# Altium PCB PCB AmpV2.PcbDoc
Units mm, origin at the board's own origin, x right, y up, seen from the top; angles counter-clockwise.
Board outline 98.3 x 139.06 mm, 2 copper layers (Top Layer, Bottom Layer); 152 components, 84 nets, 378 pads, 281 vias.
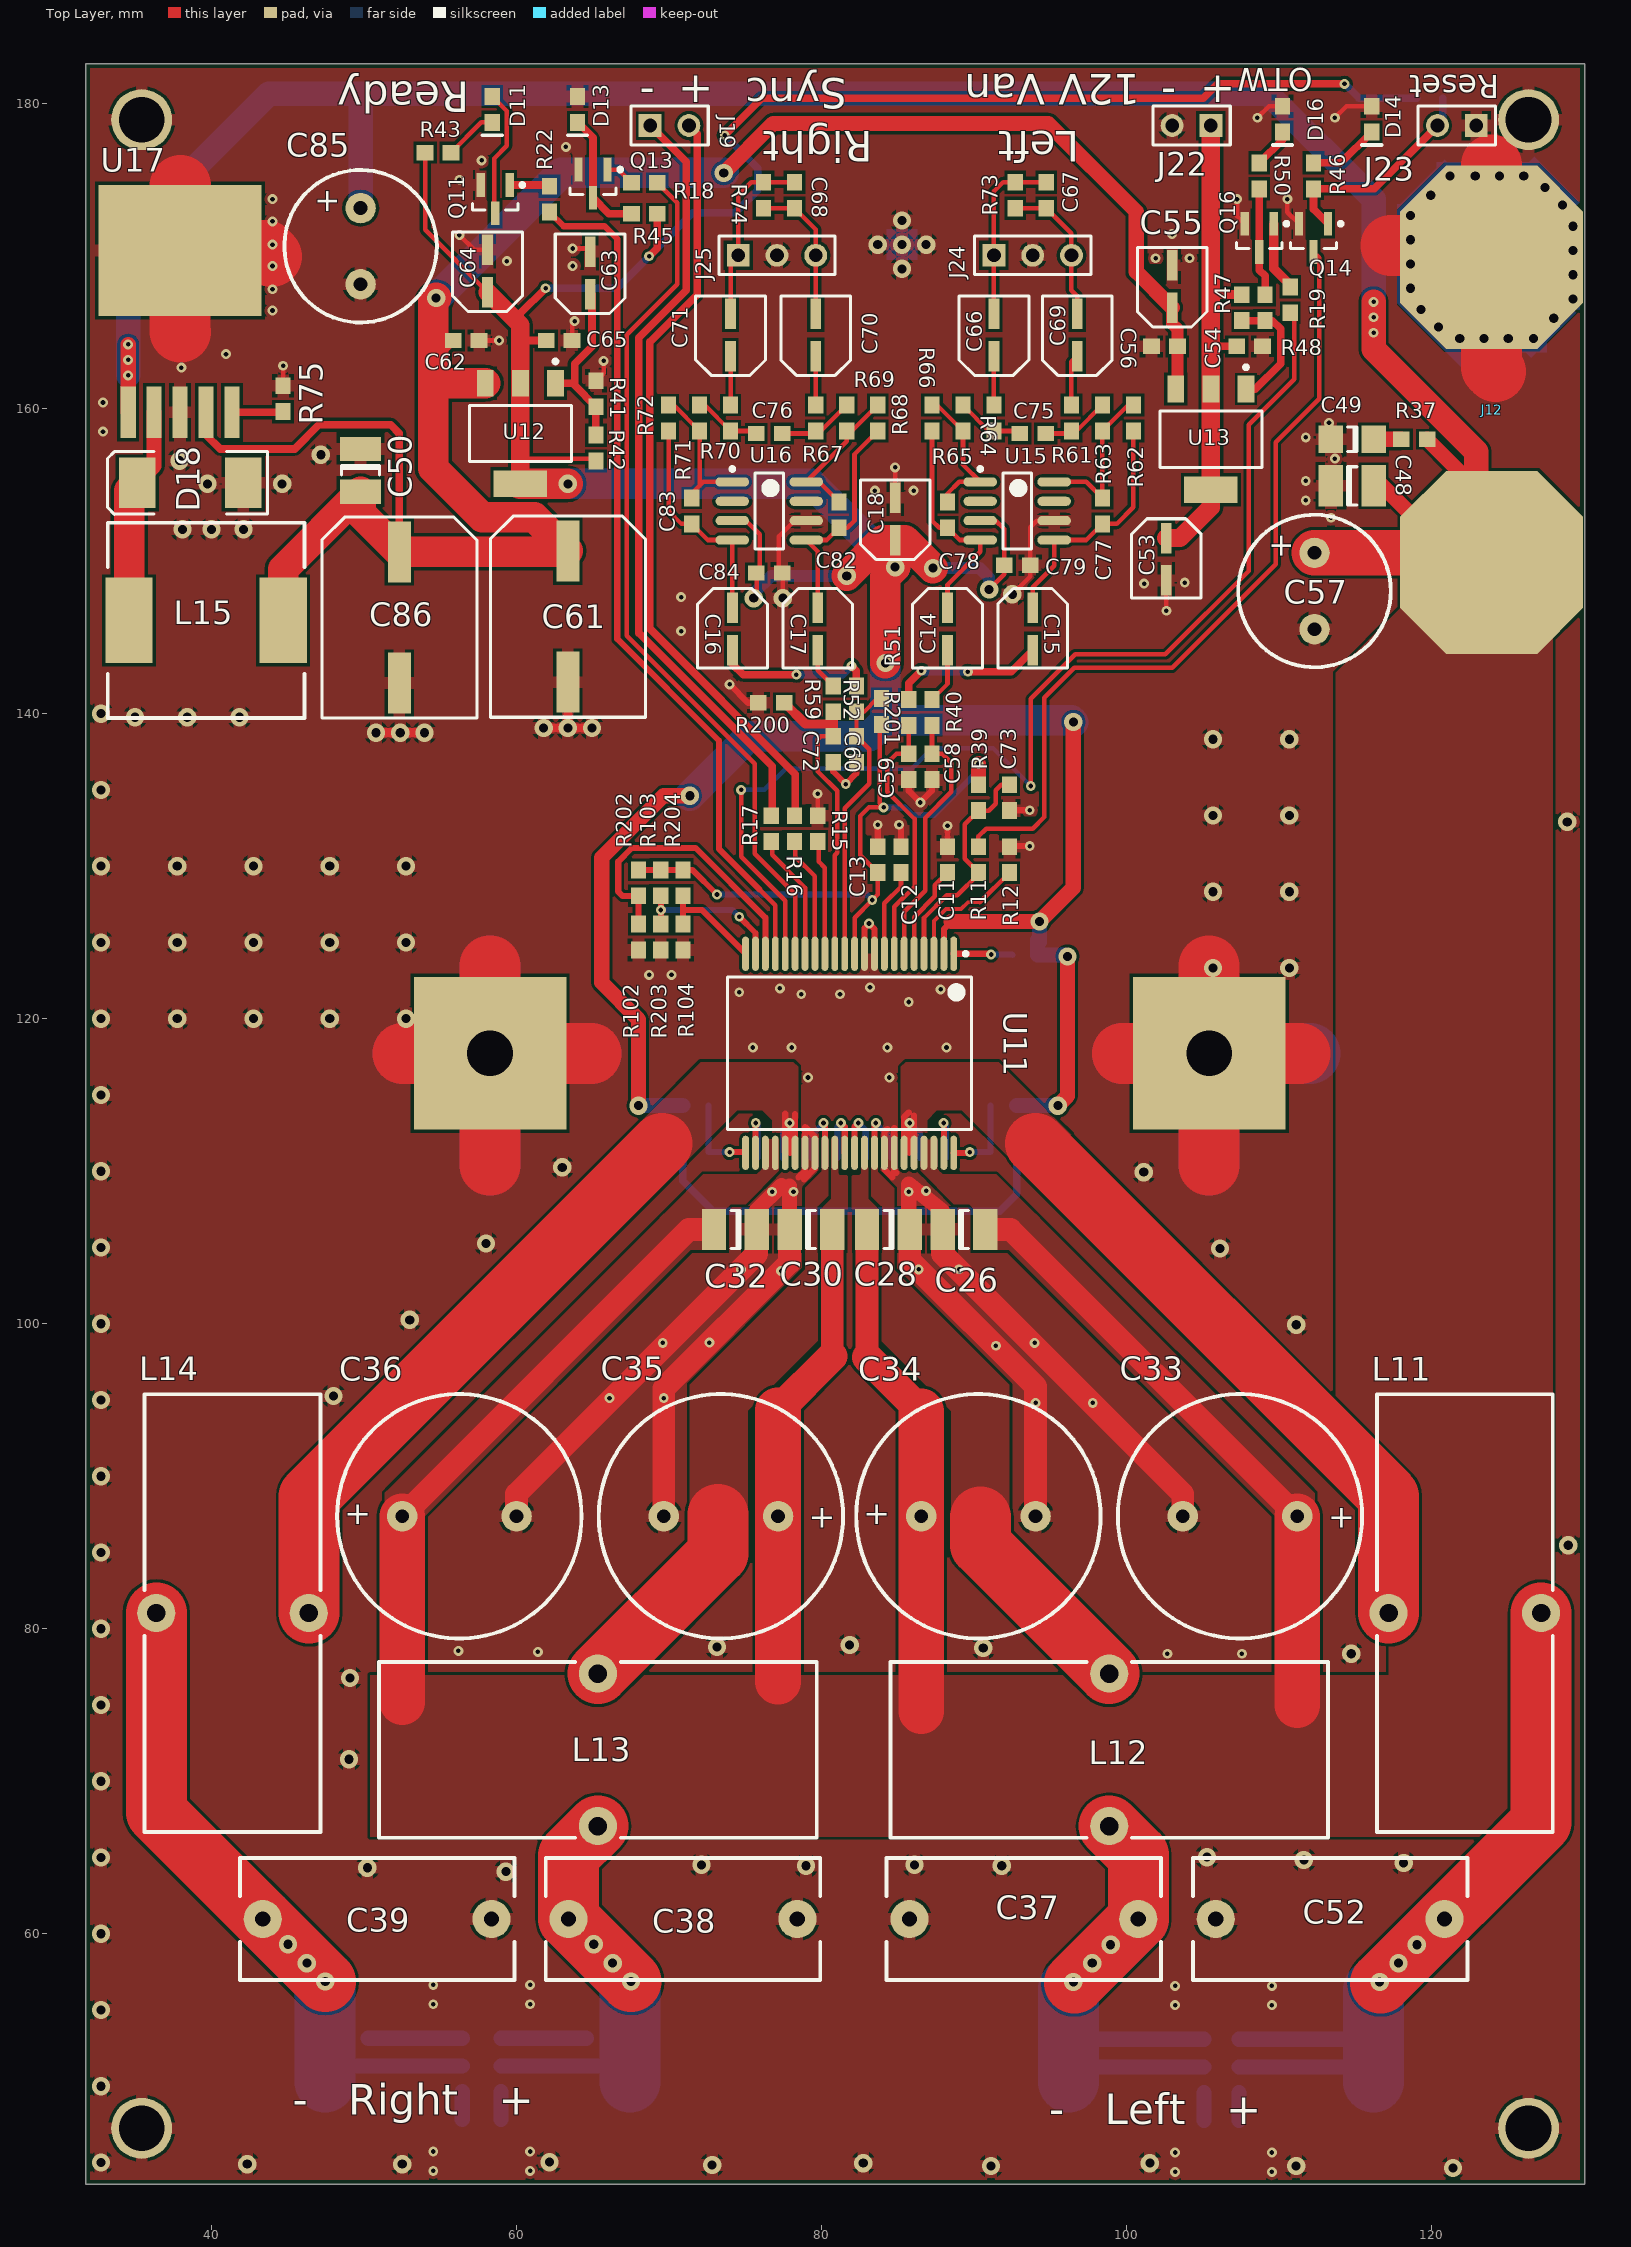
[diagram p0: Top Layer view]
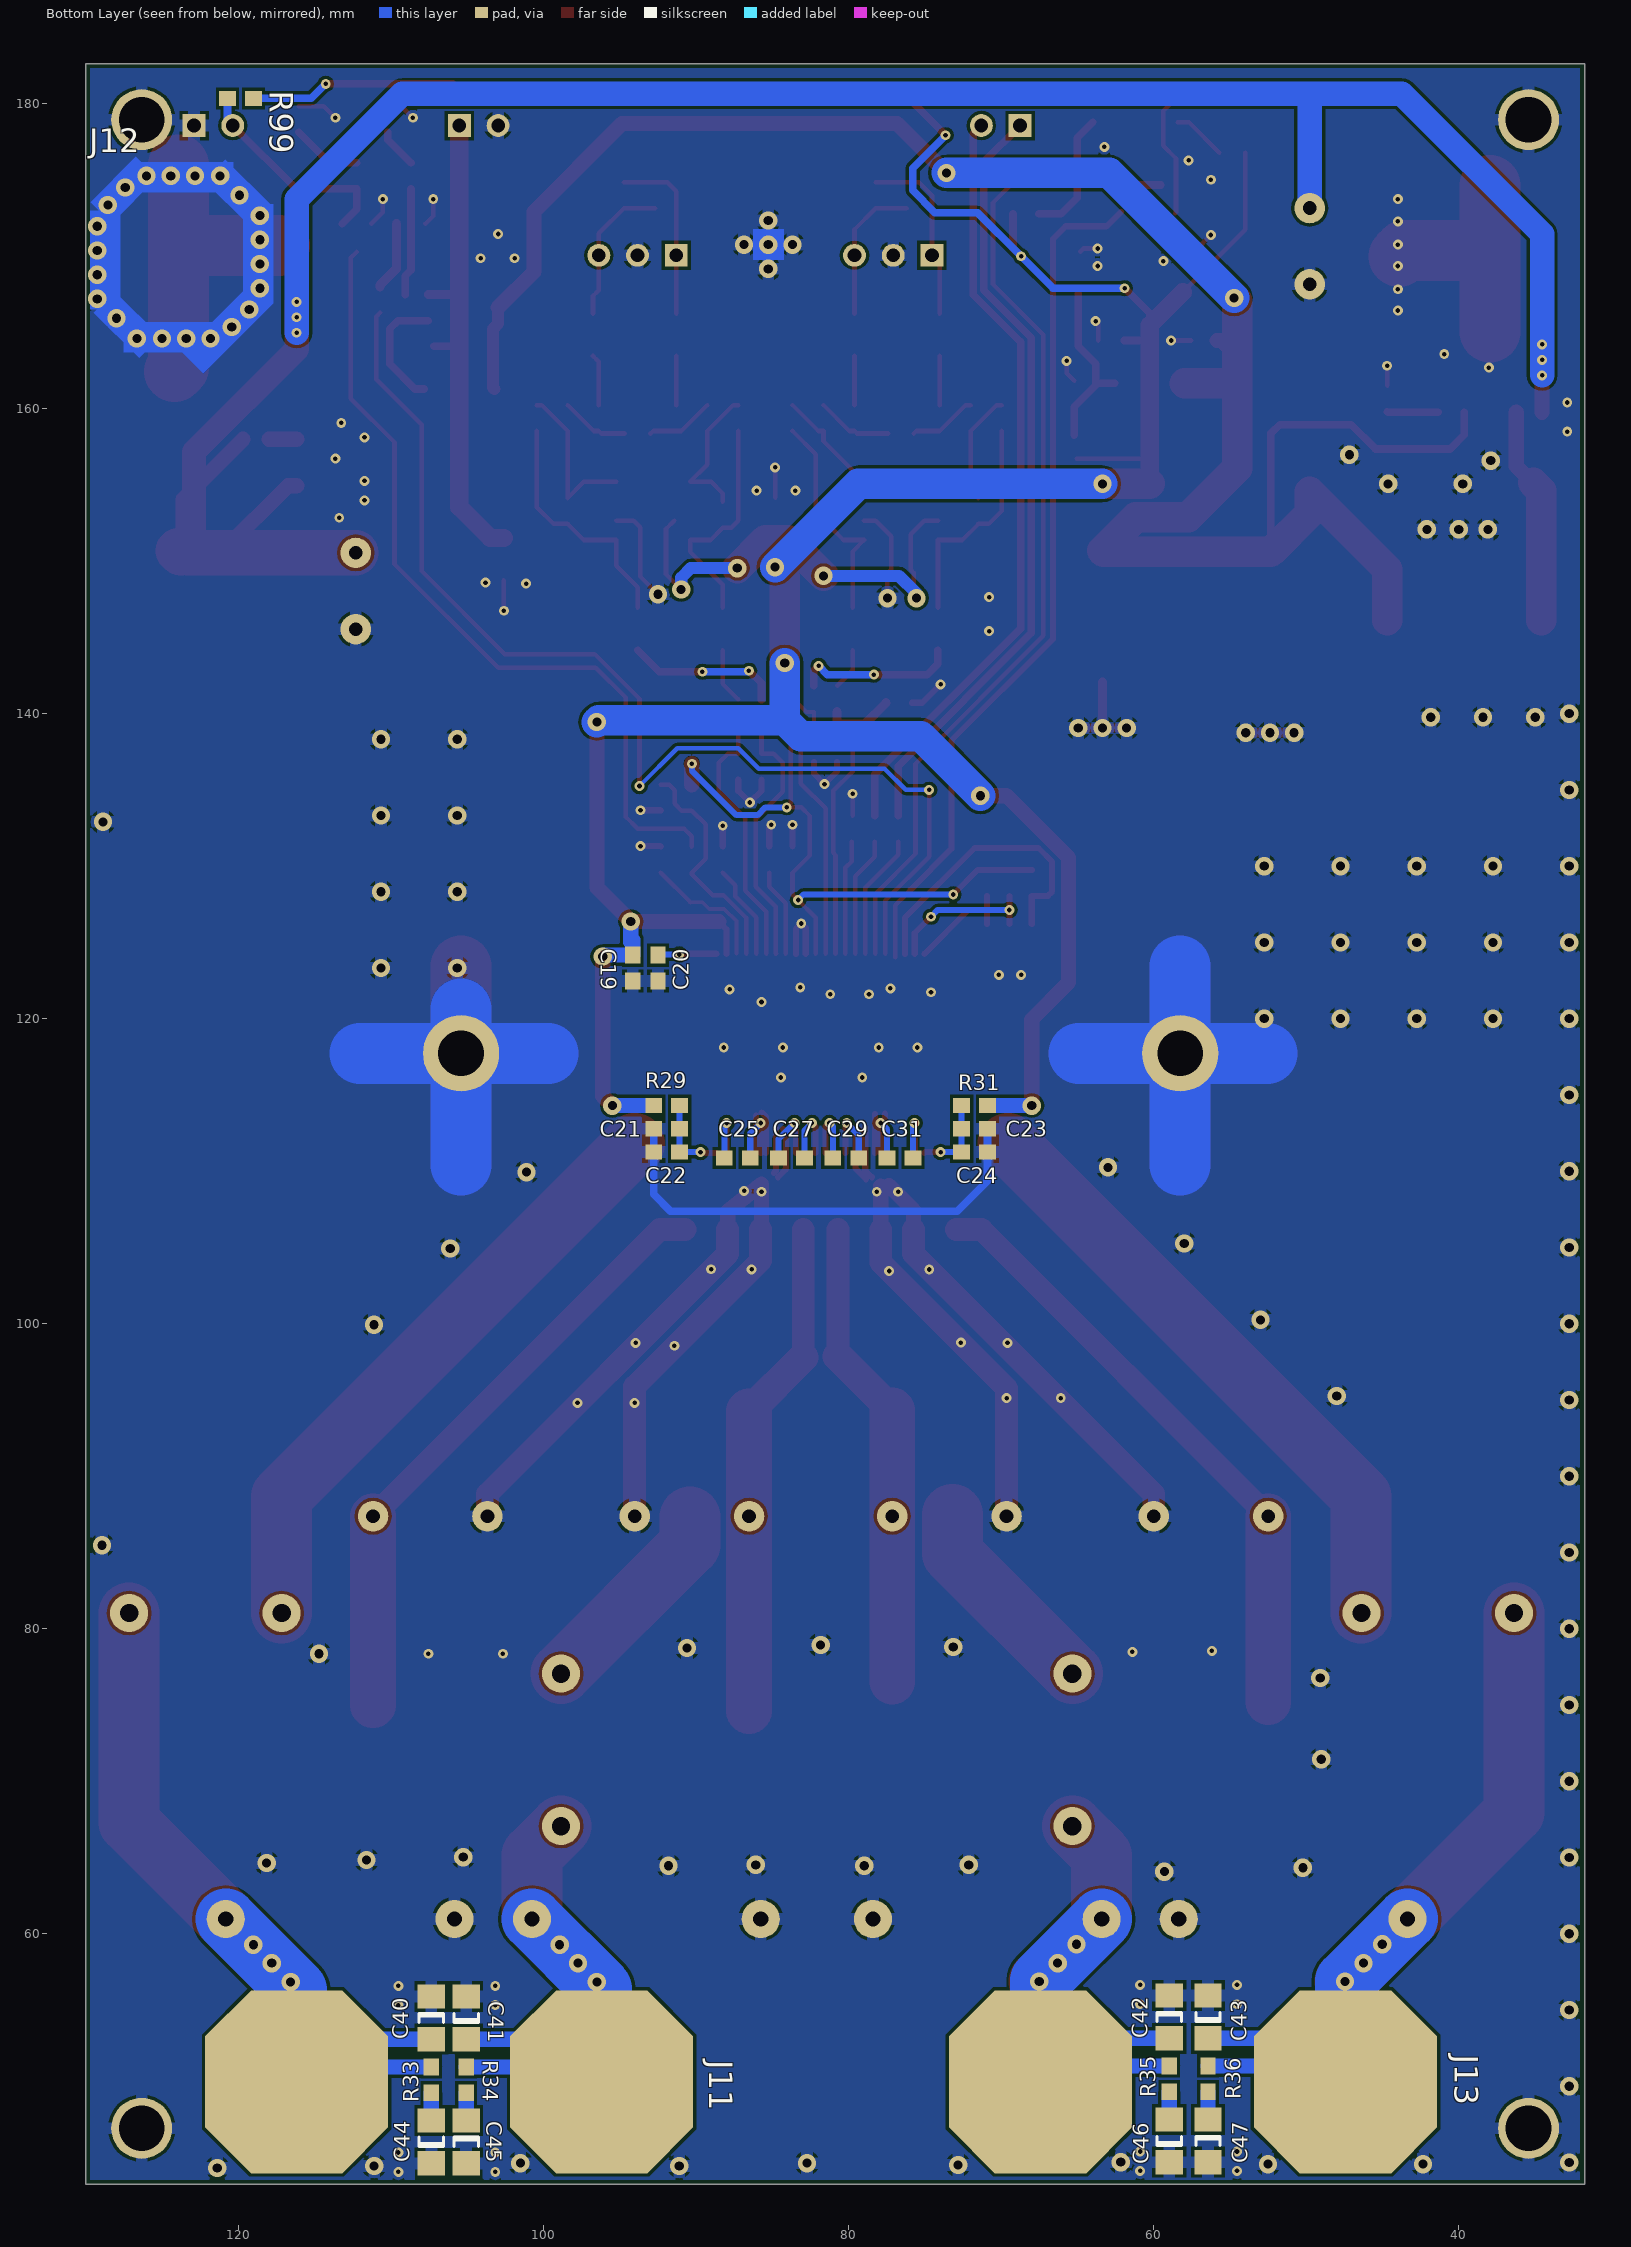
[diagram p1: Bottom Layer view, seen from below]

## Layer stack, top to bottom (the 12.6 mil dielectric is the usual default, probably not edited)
Top Layer: signal copper 0.0356
Dielectric: dielectric 0.32, FR-4, Dk 4.8
Bottom Layer: signal copper 0.0356

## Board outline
130.048,182.626 130.048,43.561 31.75,43.561 31.75,182.626

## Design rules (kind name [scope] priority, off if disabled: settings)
Clearance [All] p1: gap=0.2
ComponentClearance ComponentClearance_1 [(InComponent('J11'))] p1: gap=-10 collisioncheckmode=3 verticalgap=0.254 showdistances=FALSE
ComponentClearance [All] p2: gap=0.254 collisioncheckmode=3 verticalgap=0.254 showdistances=FALSE
Height [All] p1: minheight=0 maxheight=50 prefheight=12.7
HoleSize [All] p1: absolutevalues=TRUE maxlimit=4 minlimit=0.025 maxpercent=80.000 minpercent=20.000
MinimumSolderMaskSliver [All] p1: minsoldermaskwidth=0.15
PlaneConnect [All] p1: planeconnectstyle=Relief reliefexpansion=0.508 reliefentries=4 reliefconductorwidth=0.4 reliefairgap=0.254
PolygonConnect PolygonConnect_3 [InNet('NetC27_2')] p1: connectstyle=Direct reliefconductorwidth=0.254 reliefentries=4 polygonreliefangle="90 Angle"
PolygonConnect PolygonConnect_2 [InNet('NetC29_2')] p2: connectstyle=Direct reliefconductorwidth=0.254 reliefentries=4 polygonreliefangle="90 Angle"
PolygonConnect PolygonConnect_1 [InNet('PVDD')] p3: connectstyle=Direct reliefconductorwidth=0.254 reliefentries=4 polygonreliefangle="90 Angle"
PolygonConnect [All] p4: connectstyle=Relief reliefconductorwidth=0.8 reliefentries=4 polygonreliefangle="90 Angle"
RoomDefinition "Sheet1 AmpV2" [InComponentClass('Sheet1 AmpV2')] p1: confinementstyle=ConfineIn formatcopy=TRUE lockcomponents=FALSE outline 21.59,34.099 189.992,34.099 189.992,203.391 21.59,203.391
RoutingVias [All] p1: holewidth=0.711 width=0.8 viastyle="Through Hole" minholewidth=0.3 minwidth=0.65 maxholewidth=1 maxwidth=2
SilkscreenOverComponentPads [All] p1 off: minsilkscreentomaskgap=0.254
SolderMaskExpansion [All] p1: expansion=0.102
TestPointUsage [All] p1: valid=0 allowmultiple=FALSE
Testpoint [All] p1: side=15 testpointundercomponent=TRUE minsize=1.016 maxsize=2.54 preferedsize=1.524 minholesize=0 maxholesize=1.016 preferedholesize=0.813 testpointgrid=0.025 style=1023 order=0123456789
Width [All] p1: maxlimit=10 minlimit=0.2 preferedwidth=0.254 minimp=50.000000 maximp=50.000000 favimp=50.000000
18 further rules are at their usual default settings.

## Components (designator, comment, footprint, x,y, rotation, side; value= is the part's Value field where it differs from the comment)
C11 "Cap Semi" 1608[0603] 88.265,130.429 r90 top
C12 "Cap Semi" 1608[0603] 85.217,130.429 r90 top
C13 "Cap Semi" 1608[0603] 83.693,130.429 r90 top
C14 "SMD CAP B" "Capacitor B" 88.265,148.463 r90 top
C15 "SMD CAP B" "Capacitor B" 93.853,148.463 r90 top
C16 "SMD CAP B" "Capacitor B" 74.168,148.463 r90 top
C17 "SMD CAP B" "Capacitor B" 79.756,148.463 r90 top
C18 "SMD CAP B" "Capacitor B" 84.836,149.86 r270 top
C19 "Cap Semi" 1608[0603] 94.17,123.317 r270 bottom
C20 "Cap Semi" 1608[0603] 92.519,123.317 r270 bottom
C21 "Cap Semi" 1608[0603] 91.948,112.776 r0 bottom
C22 "Cap Semi" 1608[0603] 91.948,111.252 r0 bottom
C23 "Cap Semi" 1608[0603] 71.755,112.776 r180 bottom
C24 "Cap Semi" 1608[0603] 71.755,111.252 r180 bottom
C25 "Cap Semi" 1608[0603] 87.312,110.871 r180 bottom
C26 "Cap Semi" C1210 89.344,106.172 r0 top
C27 "Cap Semi" 1608[0603] 83.757,110.871 r0 bottom
C28 "Cap Semi" C1210 84.391,106.172 r180 top
C29 "Cap Semi" 1608[0603] 80.2,110.871 r180 bottom
C30 "Cap Semi" C1210 79.311,106.172 r0 top
C31 "Cap Semi" 1608[0603] 76.644,110.871 r0 bottom
C32 "Cap Semi" C1210 74.358,106.172 r180 top
C33 "Low ESR" Cap_RM7.5 103.695,87.376 r0 top
C34 "Low ESR" Cap_RM7.5 94.043,87.376 r180 top
C35 "Low ESR" Cap_RM7.5 69.659,87.376 r0 top
C36 "Low ESR" Cap_RM7.5 60.008,87.376 r180 top
C37 "MKP4" MKP4 100.774,60.96 r180 top
C38 "MKP4" MKP4 78.422,60.96 r180 top
C39 "MKP4" MKP4 43.37,60.96 r0 top
C40 "Cap Semi" C1206 107.379,54.483 r270 bottom
C41 "Cap Semi" C1206 105.093,54.483 r90 bottom
C42 "Cap Semi" C1206 58.991,54.546 r270 bottom
C43 "Cap Semi" C1206 56.451,54.546 r90 bottom
C44 "Cap Semi" C1206 107.379,46.355 r90 bottom
C45 "Cap Semi" C1206 105.093,46.355 r270 bottom
C46 "Cap Semi" C1206 58.991,46.418 r90 bottom
C47 "Cap Semi" C1206 56.451,46.418 r270 bottom
C48 "Cap Semi" C1210 114.808,154.94 r0 top
C49 "Cap Semi" C1206 114.808,157.988 r180 top
C50 "Cap Semi" C1210 49.784,155.956 r270 top
C52 "MKP4" MKP4 105.855,60.96 r0 top
C53 "SMD CAP B" "Capacitor B" 102.616,153.035 r90 top
C54 "Cap Semi" 1608[0603] 108.077,164.084 r180 top
C55 "SMD CAP B" "Capacitor B" 102.997,165.1 r270 top
C56 "Cap Semi" 1608[0603] 102.489,164.084 r0 top
C57 "136 RVI" CAP_47µF 112.331,145.542 r90 top
C58 "Cap Semi" 1608[0603] 87.249,136.525 r270 top
C59 "Cap Semi" 1608[0603] 85.725,136.525 r270 top
C60 "Cap Semi" 1608[0603] 82.296,137.668 r270 top
C61 "SMD CAP G" "Capacitor G" 63.373,146.368 r90 top
C62 "Cap Semi" 1608[0603] 56.706,164.465 r180 top
C63 "SMD CAP B" "Capacitor B" 64.834,165.989 r270 top
C64 "SMD CAP B" "Capacitor B" 58.102,166.116 r270 top
C65 "Cap Semi" 1608[0603] 62.801,164.465 r180 top
C66 "SMD CAP B" "Capacitor B" 91.313,161.925 r270 top
C67 "Cap Semi" 1608[0603] 94.742,173.99 r270 top
C68 "Cap Semi" 1608[0603] 78.232,173.99 r270 top
C69 "SMD CAP B" "Capacitor B" 96.774,161.925 r270 top
C70 "SMD CAP B" "Capacitor B" 79.629,161.925 r270 top
C71 "SMD CAP B" "Capacitor B" 74.041,161.925 r270 top
C72 "Cap Semi" 1608[0603] 80.772,137.668 r270 top
C73 "Cap Semi" 1608[0603] 92.329,134.493 r270 top
C75 "Cap Semi" 1608[0603] 93.853,158.369 r0 top
C76 "Cap Semi" 1608[0603] 76.581,158.369 r0 top
C77 "Cap Semi" 1608[0603] 98.425,153.289 r90 top
C78 "Cap Semi" 1608[0603] 88.265,153.035 r270 top
C79 "Cap Semi" 1608[0603] 92.837,149.733 r180 top
C82 "Cap Semi" 1608[0603] 81.153,153.035 r90 top
C83 "Cap Semi" 1608[0603] 71.501,153.289 r270 top
C84 "Cap Semi" 1608[0603] 76.581,149.225 r180 top
C85 "136 RVI" CAP_47µF 49.784,168.148 r90 top
C86 "SMD CAP G" "Capacitor G" 52.324,146.304 r90 top
D11 "SMD LED" SMD_LED_0603 58.42,180.467 r0 top
D13 "SMD LED" SMD_LED_0603 64.008,180.467 r0 top
D14 "SMD LED" SMD_LED_0603 116.078,179.832 r0 top
D16 "SMD LED" SMD_LED_0603 110.236,179.832 r0 top
D18 "30BQ060" SMC 38.608,155.13 r180 top
J11 "PADs" PADS 96.203,50.292 r0 top
J12 "PADs" PADS 123.952,169.926 r270 bottom
J13 "PADs" PADS 47.434,50.292 r0 top
J19 "Header 2" HDR1X2 68.77,178.562 r0 top
J22 "Header 2" HDR1X2 105.537,178.562 r180 top
J23 "Header 2" HDR1X2 122.936,178.562 r180 top
J24 "Header 3" HDR1X3 91.313,170.053 r0 top
J25 "Header 3" HDR1X3 74.549,170.053 r0 top
L11 "TIC-INDC-026" TIC-INDC-026(1.00) 127.191,81.026 r180 top
L12 "TIC-INDC-026" TIC-INDC-026(1.00) 98.87,67.056 r90 top
L13 "TIC-INDC-026" TIC-INDC-026(1.00) 65.341,67.056 r90 top
L14 "TIC-INDC-026" TIC-INDC-026(1.00) 36.386,81.026 r0 top
L15 "1mH Power Inductor" B82477G4105M 44.704,146.113 r180 top
Q11 "MOSFET" SOT-23 58.61,173.736 r270 top
Q13 "MOSFET" SOT-23 65.024,174.752 r270 top
Q14 "MOSFET" SOT-23 112.268,171.196 r270 top
Q16 "MOSFET" SOT-23 108.712,171.196 r270 top
R11 "Res Semi" 1608[0603] 90.297,130.429 r90 top
R12 "Res Semi" 1608[0603] 92.329,130.429 r90 top
R15 "Res Semi" 1608[0603] 79.756,132.461 r90 top
R16 "Res Semi" 1608[0603] 78.232,132.461 r90 top
R17 "Res Semi" 1608[0603] 76.708,132.461 r90 top
R18 "Res Semi" 1608[0603] 68.389,174.815 r180 top
R19 "Res Semi" 1608[0603] 110.744,167.132 r90 top
R22 "Res Semi" 1608[0603] 62.166,173.736 r90 top
R29 "Res Semi" 1608[0603] 91.948,114.3 r0 bottom
R31 "Res Semi" 1608[0603] 71.755,114.3 r180 bottom
R33 "Res Semi" 1608[0603] 107.379,50.419 r90 bottom
R34 "Res Semi" 1608[0603] 105.093,50.419 r270 bottom
R35 "Res Semi" 1608[0603] 58.991,50.482 r90 bottom
R36 "Res Semi" 1608[0603] 56.451,50.482 r270 bottom
R37 "Res Semi" 1608[0603] 118.872,157.988 r180 top
R39 "Res Semi" 1608[0603] 90.297,134.493 r90 top
R40 "Res Semi" 1608[0603] 87.249,140.081 r90 top
R41 "Res Semi" 1608[0603] 65.215,160.972 r270 top
R42 "Res Semi" 1608[0603] 65.215,157.416 r270 top
R43 "Res Semi" 1608[0603] 54.864,176.784 r180 top
R45 "Res Semi" 1608[0603] 68.389,172.784 r0 top
R46 "Res Semi" 1608[0603] 112.268,175.26 r270 top
R47 "Res Semi" 1608[0603] 107.569,166.624 r90 top
R48 "Res Semi" 1608[0603] 109.093,166.624 r270 top
R50 "Res Semi" 1608[0603] 108.712,175.26 r270 top
R51 "Res Semi" 1608[0603] 85.725,140.081 r90 top
R52 "Res Semi" 1608[0603] 82.296,140.97 r90 top
R59 "Res Semi" 1608[0603] 80.772,140.97 r90 top
R61 "Res Semi" 1608[0603] 96.393,159.385 r90 top
R62 "Res Semi" 1608[0603] 100.457,159.385 r90 top
R63 "Res Semi" 1608[0603] 98.425,159.385 r90 top
R64 "Res Semi" 1608[0603] 91.313,159.385 r90 top
R65 "Res Semi" 1608[0603] 89.281,159.385 r90 top
R66 "Res Semi" 1608[0603] 87.249,159.385 r270 top
R67 "Res Semi" 1608[0603] 79.629,159.385 r90 top
R68 "Res Semi" 1608[0603] 83.693,159.385 r90 top
R69 "Res Semi" 1608[0603] 81.661,159.385 r90 top
R70 "Res Semi" 1608[0603] 74.041,159.385 r90 top
R71 "Res Semi" 1608[0603] 72.009,159.385 r90 top
R72 "Res Semi" 1608[0603] 69.977,159.385 r270 top
R73 "Res Semi" 1608[0603] 92.71,173.99 r270 top
R74 "Res Semi" 1608[0603] 76.2,173.99 r270 top
R75 "Res Semi" 1608[0603] 44.704,160.655 r270 top
R99 "Res Semi" 1608[0603] 119.888,180.34 r180 bottom
R102 "Res Semi" 1608[0603] 68.008,125.349 r90 top
R103 "Res Semi" 1608[0603] 69.469,128.905 r270 top
R104 "Res Semi" 1608[0603] 70.929,125.349 r90 top
R200 "Res Semi" 1608[0603] 76.708,140.716 r0 top
R201 "Res Semi" 1608[0603] 83.947,140.144 r270 top
R202 "Res Semi" 1608[0603] 68.008,128.905 r270 top
R203 "Res Semi" 1608[0603] 69.469,125.349 r90 top
R204 "Res Semi" 1608[0603] 70.929,128.905 r270 top
U11 "TAS5630DKD" SOP65P1420X360-44N 81.852,117.729 r270 top
U12 "LM317MSTT3" 318E-04 60.261,158.369 r180 top
U13 "LM317MSTT3" 318E-04 105.537,157.988 r180 top
U15 "Op-Amp" SOP127P600X175-8N 92.837,153.289 r0 top
U16 "Op-Amp" SOP127P600X175-8N 76.581,153.289 r0 top
U17 "DC/DC" TL2575HV-15 34.544,159.766 r0 top

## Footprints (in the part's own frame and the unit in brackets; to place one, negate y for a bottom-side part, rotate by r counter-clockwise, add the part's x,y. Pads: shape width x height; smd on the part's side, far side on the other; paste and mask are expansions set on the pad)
318E-04 [mm] "SOT-223/SC-73; 4 Leads; Body 6.7 x 7.3 mm, inc. leads (LxW max)"
  rect 1.1x1.75 smd: 1(-2.3,-3.3) 2(0,-3.3) 3(2.3,-3.3)
  rect 3.5x1.75 smd: 4(0,3.3)
  silkscreen extent -3.35,-4.85 3.35,1.85
1608[0603] [mm] "Chip Capacitor; Body 1.6 x 0.8 mm (LxW typ)"
  rect 1.1x1 smd: 1(-0.85,0) 2(0.85,0)
B82477G4105M [mm] "1mH Power Inductor"
  rect 3.1x5.6 smd: 0(0,0) 1(10.1,0)
  silkscreen extent -1.4,-6.4 11.5,6.4
C1206 [mm] "Chip Capacitor; Body 3.2 x 1.6 mm (LxW typ)"
  rect 1.6x1.8 smd: 1(-1.4,0) 2(1.4,0)
  silkscreen extent -0.3,-0.8 0.3,0.8
C1210 [mm] "Chip Capacitor; Body 3.2 x 2.5 mm (LxW typ)"
  rect 1.6x2.7 smd: 1(-1.4,0) 2(1.4,0)
  silkscreen extent -0.3,-1.25 0.3,1.25
CAP_47µF [mm]
  round 2 hole 0.9: 1(0,0) 2(5,0)
  silkscreen extent -2.5,-5 7.5,5
Cap_RM7.5 [mm]
  round 2 hole 0.9: 1(0,0) 2(7.5,0)
  silkscreen extent -4.26,-8.01 11.76,8.01
"Capacitor B" [mm]
  rect 2x0.7 smd: 1(-4.3,0) 2(-1.524,0)
  silkscreen extent -5.46,-2.29 -0.25,2.29
"Capacitor G" [mm]
  rect 4x1.5 smd: 1(-4.3,0) 2(4.3,0)
  silkscreen extent -6.6,-5.08 6.6,5.08
HDR1X2 [mm] "Connector; Header; 2 Position"
  rect 1.5x1.5 hole 0.9: 1(0,0)
  round 1.5 hole 0.9: 2(2.54,0)
  silkscreen extent -1.27,-1.27 3.81,1.27
HDR1X3 [mm] "Connector; Header; 3 Position"
  rect 1.5x1.5 hole 0.9: 1(0,0)
  round 1.5 hole 0.9: 2(2.54,0) 3(5.08,0)
  silkscreen extent -1.27,-1.27 6.35,1.27
MKP4 [mm]
  round 2.5 hole 1: 1(0,0) 2(15,0)
  silkscreen extent -1.5,-4 16.5,4
PADS [mm]
  oct 12x12 smd far side: 1(0,0) 2(20,0)
SMC [mm] "DO-214-AB/SMC; 2 C-Bend Leads; Body 7.9 x 5.9 mm, inc. leads (LxW)"
  rect 2.4x3.3 smd: 1(-3.475,0) 2(3.475,0)
  silkscreen extent -5.07,-2.05 5.43,2.05
SMD_LED_0603 [mm]
  rect 1x1.1 smd: 1(0,0) 2(0,-1.7)
  silkscreen extent -0.64,-2.54 0.64,-2.54
SOP65P1420X360-44N [mm] "SOP, 44-Leads, Body 16,0x11,1mm (max), Pitch 0,65mm, IPC Medium Density"
  oval 2.25x0.45 smd: 1(-6.525,6.825) 2(-6.525,6.175) 3(-6.525,5.525) 4(-6.525,4.875) 5(-6.525,4.225) 6(-6.525,3.575) 7(-6.525,2.925) 8(-6.525,2.275) 9(-6.525,1.625) 10(-6.525,0.975) 11(-6.525,0.325) 12(-6.525,-0.325) 13(-6.525,-0.975) 14(-6.525,-1.625) 15(-6.525,-2.275) 16(-6.525,-2.925) 17(-6.525,-3.575) 18(-6.525,-4.225) 19(-6.525,-4.875) 20(-6.525,-5.525) 21(-6.525,-6.175) 22(-6.525,-6.825) 23(6.525,-6.825) 24(6.525,-6.175) 25(6.525,-5.525) 26(6.525,-4.875) 27(6.525,-4.225) 28(6.525,-3.575) 29(6.525,-2.925) 30(6.525,-2.275) 31(6.525,-1.625) 32(6.525,-0.975) 33(6.525,-0.325) 34(6.525,0.325) 35(6.525,0.975) 36(6.525,1.625) 37(6.525,2.275) 38(6.525,2.925) 39(6.525,3.575) 40(6.525,4.225) 41(6.525,4.875) 42(6.525,5.525) 43(6.525,6.175) 44(6.525,6.825)
  silkscreen extent -6.65,-8 5,8, body extent -5.55,-8 5.55,8, height 3.6
SOP127P600X175-8N [mm] "SOP, 8-Leads, Body 5,0x4,0mm (max), Pitch 1,27mm, IPC Medium Density"
  oval 2.2x0.6 smd: 1(-2.425,1.905) 2(-2.425,0.635) 3(-2.425,-0.635) 4(-2.425,-1.905) 5(2.425,-1.905) 6(2.425,-0.635) 7(2.425,0.635) 8(2.425,1.905)
  silkscreen extent -2.55,-2.5 0.93,2.88, body extent -2,-2.5 2,2.5, height 1.75
SOT-23 [mm] "SOT23, 3-Leads, Body 3,0x2,6mm (max), Pitch 0,95mm, IPC Medium Density"
  rect 1.55x0.55 smd: 1(-0.925,0.95) 2(-0.925,-0.95) 3(0.925,0)
  silkscreen extent -1.05,-1.5 0.7,1.9, body extent -0.7,-1.5 0.7,1.5, height 1.1
TIC-INDC-026(1.00) [mm]
  round 2.5 hole 1.2: 1(0,0) 2(10,0)
  silkscreen extent -0.76,-14.35 10.76,14.35
TL2575HV-15 [mm] "DC/DC Converter"
  rect 1x3.4 smd: 1(0,0) 2(1.7,0) 3(3.4,0) 4(5.1,0) 5(6.8,0)
  rect 10.7x8.6 smd: 6(3.4,10.6)

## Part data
C11 C12 C13 C19 C20 C21 C22 C23 C24 C25 C26 C27 C28 C29 C30 C31 C32 C40 C41 C42 C43 C44 C45 C46 C47 C48 C49 C50 C54 C56 C58 C59 C60 C62 C65 C67 C68 C72 C73 C75 C76 C77 C78 C79 C82 C83 C84: "Capacitor (Semiconductor SIM Model)"
C14 C15 C16 C17 C18 C53 C55 C63 C64 C66 C69 C70 C71: "VF 10/16 C-B"
C33 C34 C35 C36: library part Cap_1000µF, "RAD FC 1.000/63"
C61 C86: "VF 470/25 K-G"
D18: "Schottky Rectifier"
J11 J12 J13: library part PAD
J19 J22 J23: "Header, 2-Pin"
J24 J25: "Header, 3-Pin"
L15: library part B82477G4105M
Q11 Q13 Q14 Q16: library part 2N7002
R11 R12 R15 R16 R17 R18 R19 R22 R29 R31 R33 R34 R35 R36 R37 R39 R40 R41 R42 R43 R45 R46 R47 R48 R50 R51 R52 R59 R61 R62 R63 R64 R65 R66 R67 R68 R69 R70 R71 R72 R73 R74 R75 R99 R102 R103 R104 R200 R201 R202 R203 R204: "Semiconductor Resistor"
U11: "TAS5630DKD 2x300W Audio-Amp"
U12 U13: "Three-Terminal Adjustable Output Positive Voltage Regulator"
U15 U16: library part OPA1632
U17: library part TL2575HV-15, "1A Stepdown"

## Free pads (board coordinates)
  round 4 hole 3: ""(35.433,47.244) ""(35.433,178.943) ""(126.365,47.244) ""(126.365,178.943)
  rect 10x10 / inner rect 10x10 / far side round 5 hole 3: ""(58.277,117.729) ""(105.426,117.729)

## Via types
v1: diameter 1.2, hole 0.6, Top Layer to Bottom Layer, 142 vias
v2: diameter 0.65, hole 0.3, Top Layer to Bottom Layer, 135 vias
v3: diameter 1.2, hole 0.6, Top Layer to Bottom Layer, tented top, 3 vias
v4: diameter 0.65, hole 0.3, Top Layer to Bottom Layer, tented top, 1 vias

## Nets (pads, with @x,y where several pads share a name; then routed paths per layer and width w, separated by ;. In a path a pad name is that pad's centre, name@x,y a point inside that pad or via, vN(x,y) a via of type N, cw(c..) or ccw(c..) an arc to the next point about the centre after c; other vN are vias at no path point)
+12V: C18.2 C19.1 C64.2 C65.2 C79.2 C84.2 R29.2 R31.2 R42.2 R43.2 R45.2 R99.2 U11.2 U12.2 U12.4 U15.3 U16.3 | length 268.8
  Top Layer w0.3: R43.2 54.014,171.729 C64.2 ; 60.261,156.718 R42.2@65.063,156.718 ; U16.3 75.057,152.654 75.946,151.765 75.946,149.44 C84.2 75.755,149.2 75.755,147.764 v1(75.565,147.574) ; v1(90.995,148.145) 91.987,149.137 C79.2 91.987,152.107 U15.3@91.44,152.654
  Top Layer w0.4: U11.2 88.026,125.872 88.519,126.365
  Top Layer w0.5: 60.261,164.465 C65.2 ; 60.261,165.481 60.261,166.243 v2(61.912,167.894) ; v2(68.707,169.989) 69.24,170.522 R45.2 ; v2(73.66,177.927) 76.073,180.34 105.029,180.34 105.981,181.292 v2(114.3,181.292)
  Top Layer w1: v1(68.008,114.3) 68.008,119.951 65.596,122.364 65.596,130.556 69.659,134.62 v1(71.374,134.62) ; 88.519,126.365 v1(94.297,126.365) 96.52,128.588 v1(96.52,139.446) ; v1(95.504,114.3) 96.139,114.935 v1(96.139,124.079)
  Top Layer w1.2: C64.2 60.261,165.481 60.261,164.465 U12.2 60.261,156.718 U12.4
  Top Layer w2: U12.4 v1(63.373,155.069) ; v1(81.661,149.034) 84.01,151.384 C18.2 ; v3(84.201,143.32) 84.201,148.971 v1(84.836,149.606) C18.2 ; v1(87.312,149.542) 85.471,151.384 C18.2
  Bottom Layer w0.5: v2(61.912,167.894) 66.611,167.894 v2(68.707,169.989) 71.564,172.847 74.358,172.847 75.819,174.308 75.819,175.768 v2(73.66,177.927) ; v2(114.3,181.292) 115.252,180.34 R99.2
  Bottom Layer w0.8: v1(75.565,147.574) 75.565,147.892 76.708,149.034 v1(81.661,149.034) ; v1(87.312,149.542) 90.361,149.542 90.995,148.907 v1(90.995,148.145)
  Bottom Layer w1: v1(68.008,114.3) R31.2 ; R29.2 v1(95.504,114.3) ; v1(94.297,126.365) 94.297,125.031 94.17,125.158 C19.1 v1@96.051,124.167
  Bottom Layer w2: v1(63.373,155.069) 79.373,155.069 v1(84.836,149.606) ; v1(71.374,134.62) 75.272,138.518 83.146,138.518 84.201,139.573 ; v3(84.201,143.32) 84.201,139.573 ; v1(96.52,139.446) 96.393,139.573 84.201,139.573
+15V: C50.2 C55.2 C56.2 C61.2 C62.2 C86.2 L15.0 U12.3 U13.3 U17.4 | length 143.2
  Top Layer w0.5: U17.4 39.644,158.286 40.576,157.353 45.466,157.353 47.053,158.94 51.752,158.94 52.324,158.369 C86.2
  Top Layer w0.8: C55.2 102.997,165.569 103.339,165.227 C56.2 103.339,161.39 U13.3
  Top Layer w1: 54.546,163.449 55.562,164.465 C62.2 ; v1(73.596,175.451) 76.835,178.689 94.869,178.689 100.647,172.91 100.647,168.974 C55.2
  Top Layer w2: L15.0 44.704,149.476 C50.2 49.784,153.144 C86.2 63.309,150.604 C61.2 61.172,152.869 57.761,152.869 54.546,156.083 54.546,161.862 ; v1(54.737,167.259) 54.546,167.069 54.546,163.449 54.546,161.862 ; U12.3 54.739,161.669 54.546,161.862
  Bottom Layer w2: v1(54.737,167.259) 62.928,175.451 v1(73.596,175.451)
GND: C11.2 C12.2 C13.2 C18.1 C19.2 C20.2 C21.2 C22.2 C23.2 C24.2 C26.1 C28.1 C30.1 C32.1 C33.1 C34.1 C35.1 C36.1 C37.2 C38.1 C39.2 C40.1 C41.2 C42.1 C43.2 C44.1 C45.2 C46.1 C47.2 C48.1 C49.2 C50.1 C52.1 C53.1 C54.1 C55.1 C56.1 C57.1 C58.2 C59.2 C60.2 C61.1 C62.1 C63.1 C64.1 C65.1 C72.2 C73.2 C79.1 C84.1 C85.1 C86.1 D13.1 D14.1 D16.1 D18.1 J12.1 J22.2 J23.1 J24.2 J25.2 pad. Q11.2 Q13.2 Q14.2 Q16.2 R12.2 R15.2 R41.1 R75.1 R102.1 R104.1 R200.1 R203.1 U11.9 U11.10 U11.29 U11.30 U11.37 U11.38 U15.6 U16.6 U17.3 U17.6 | length 366.3
  Top Layer w0.3: R75.1 v2(44.704,162.814) ; v2(56.261,171.386) 57.232,170.416 C64.1 ; C62.1 v2(58.864,164.465) ; C65.1 63.651,165.569 v2(63.817,165.735) ; v2(63.691,170.498) 64.625,170.498 C63.1 ; R41.1 65.722,162.33 v2(65.722,163.131) ; v1(77.47,147.574) 77.47,149.186 C84.1 77.216,149.44 77.216,151.638 78.232,152.654 U16.6 ; R15.2 v2(79.756,134.747) ; C18.1 v2(84.836,156.147) ; v1(92.519,147.828) 93.687,148.995 C79.1 93.687,152.234 94.107,152.654 U15.6 ; v2(102.616,146.749) C53.1 ; v2(107.251,173.736) 107.251,172.632 Q16.2 ; v2(108.585,179.07) 109.347,179.832 D16.1 ; v2(110.553,173.736) 110.553,172.886 Q14.2 ; v2(113.665,179.07) 114.427,179.832 D14.1
  Top Layer w0.4: v2(73.977,141.922) 75.184,140.716 R200.1 ; 78.486,109.601 78.926,110.041 U11.29 78.926,112.899 79.577,112.249 U11.30 79.577,110.184 78.867,109.474 ; C72.2 80.772,136.207 v2(81.597,135.382) 82.296,136.081 C60.2 ; U11.10 82.826,125.943 v2(83.121,126.238) 83.477,125.883 U11.9 ; C13.2 v2(83.693,132.715) ; 84.328,112.776 84.127,112.575 U11.37 84.127,110.12 84.645,109.601 ; 84.777,112.835 U11.38 84.777,110.023 84.904,109.896 ; v2(85.09,132.715) 85.217,132.588 C12.2 ; C59.2 85.725,134.938 v2(86.487,134.175) 87.249,134.938 C58.2 ; C11.2 v2(88.265,132.651) ; R12.2 92.368,131.318 v2(93.662,131.318) ; C73.2 92.354,133.667 v2(93.662,133.667)
  Top Layer w0.6: v1(50.8,138.748) v1(52.387,138.748) v1(53.975,138.748) ; v1(61.785,139.065) v1(63.373,139.065) ; C61.1 v1(63.373,139.065) ; v1(64.96,139.065) v1(63.373,139.065)
  Top Layer w1: C32.1 75.758,107.445 77.375,109.061 ; C30.1 77.912,109.029 ; C28.1 85.725,106.238 85.725,109.144 87.945,107.381 C26.1
  Top Layer w1.5: C36.1 60.008,88.837 75.758,104.587 C32.1 ; C35.1 69.659,95.758 77.912,104.01 C30.1 ; C28.1 85.791,104.137 94.043,95.885 C34.1 ; C26.1 87.945,104.587 103.695,88.837 C33.1
  Top Layer w2: pad.@54.8,117.792 pad.@54.864,117.729 ; pad.@58.277,114.824 pad.@58.483,114.617 ; pad.@61.912,117.729 pad.@62.103,117.919 ; pad.@102.044,117.729 pad.@105.426,117.729 ; pad.@105.41,114.681 105.426,114.697 pad.@105.426,117.729 ; pad.@105.41,120.65 105.426,120.634 pad.@105.426,117.729 ; pad.@108.458,117.729 pad.@105.426,117.729
  Top Layer w4: 37.973,165.036 37.944,165.065 U17.6 ; U17.6@37.973,174.625 37.944,174.596 U17.6 ; 43.942,169.989 43.566,170.366 U17.6 ; 52.578,117.729 pad.@58.277,117.729 ; 58.277,110.41 pad.@58.277,117.729 ; 58.277,123.46 pad.@58.277,117.729 ; 64.897,117.729 pad.@58.277,117.729 ; 99.728,117.729 pad.@105.426,117.729 ; 105.426,110.41 pad.@105.426,117.729 ; v1@105.426,123.46 pad.@105.426,117.729 ; 111.379,117.729 pad.@105.426,117.729 ; 117.348,170.688 J12.1@123.952,170.688 ; 123.952,175.958 J12.1@123.952,170.688 ; 124.206,162.433 123.952,162.687 J12.1@123.952,170.688
  Bottom Layer w0.5: C23.2 C24.2 70.905,109.372 72.898,107.379 91.694,107.379 92.798,108.483 C22.2 C21.2
  Bottom Layer w4: 52.578,117.729 pad.@58.277,117.729 ; 58.277,110.41 pad.@58.277,117.729 ; 58.277,123.46 pad.@58.277,117.729 ; 64.897,117.729 pad.@58.277,117.729 ; 99.728,117.729 pad.@105.426,117.729 ; 105.426,110.41 pad.@105.426,117.729 ; 105.426,120.65 pad.@105.426,117.729 ; 112.047,117.729 pad.@105.426,117.729
  other v1: 121.412,44.64 91.123,44.767 111.125,44.767 72.834,44.831 42.355,44.895 52.514,44.895 82.74,44.958 101.536,44.958 32.766,45 62.166,45.021 32.766,50 32.766,55 32.766,60 59.309,64.072 50.228,64.325 78.994,64.453 91.821,64.453 72.136,64.516 86.106,64.516 118.173,64.643 111.633,64.834 32.766,65 105.283,65.024 32.766,70 49.022,71.438 32.766,75 49.085,76.772 114.745,78.359 90.614,78.74 73.152,78.803 81.852,78.93 32.766,80 32.766,85 128.969,85.471 32.766,90 32.766,95 48.008,95.252 111.139,99.935 32.766,100 53.008,100.252 106.139,104.935 32.766,105 58.008,105.252 101.139,109.935 32.766,110 63.008,110.252 32.766,115 32.766,120 37.766,120 42.766,120 47.766,120 52.766,120 105.68,123.319 110.68,123.319 32.766,125 37.766,125 42.766,125 47.766,125 52.766,125 105.68,128.319 110.68,128.319 32.766,130 37.766,130 42.766,130 47.766,130 52.766,130 128.905,132.905 105.68,133.319 110.68,133.319 32.766,135 105.68,138.319 110.68,138.319 34.989,139.763 38.417,139.763 41.846,139.763 32.766,140 38.1,152.082 40.005,152.082 42.1,152.082 44.64,155.067 47.18,156.972 121.856,164.592 123.444,164.592 125.031,164.592 126.682,164.592 120.459,165.354 128.016,165.925 119.316,166.497 129.286,167.195 118.618,167.894 129.286,168.783 85.281,169.164 118.618,169.481 129.286,170.37 83.693,170.751 85.281,170.751 86.868,170.751 118.618,171.069 129.286,171.958 85.281,172.339 118.618,172.656 128.588,173.355 119.951,173.99 127.444,174.498 121.221,175.26 122.872,175.26 124.46,175.26 126.047,175.26
  other v2: 103.188,44.387 109.537,44.387 54.546,44.45 60.896,44.45 103.188,45.657 109.537,45.657 54.546,45.72 60.896,45.72 103.188,55.315 109.537,55.315 54.546,55.378 60.896,55.378 103.188,56.585 109.537,56.585 54.546,56.648 60.896,56.648 102.679,78.359 107.569,78.359 61.404,78.486 56.197,78.549 94.043,94.805 97.79,94.805 66.103,95.123 69.659,95.123 91.44,98.552 69.596,98.742 72.657,98.755 93.98,98.742 77.354,103.453 74.727,103.556 86.372,103.557 89.027,103.569 76.772,108.648 78.168,108.648 85.725,108.648 86.868,108.712 79.121,116.141 84.455,116.141 75.501,118.11 78.041,118.11 84.328,118.11 88.201,118.11 85.725,121.094 78.676,121.602 81.216,121.602 74.612,121.73 87.82,121.92 77.279,121.983 83.185,122.047 68.707,122.872 70.168,122.872 70.802,145.415 70.802,147.637 101.155,148.526 103.822,148.59 113.411,152.844 111.76,153.987 83.502,154.623 86.042,154.623 111.76,155.257 113.665,156.718 111.76,158.115 32.893,158.496 113.284,159.067 32.893,160.401 38.036,162.687 40.957,163.576 44.005,166.433 44.005,167.831 44.005,169.355 63.691,169.355 59.372,169.672 101.917,169.862 104.14,169.862 44.005,170.751 102.997,171.45 44.005,172.275 44.005,173.736 56.261,175.006 57.721,176.276 63.246,177.165
  other v3: 39.751,155.067 37.91,156.591
NetC11_1: C11.1 U11.5 | length 6.2
  Top Layer w0.3: U11.5 86.077,126.662 87.439,128.025 87.439,128.754 C11.1
NetC12_1: C12.1 U11.8 | length 5.8
  Top Layer w0.3: U11.8 84.127,127.561 85.217,128.651 C12.1
NetC14_1: C14.1 R40.2 | length 3.7
  Top Layer w0.3: R40.2 88.265,141.947 C14.1
NetC14_2: C14.2 C78.2 R66.2 U15.4 | length 14.9
  Top Layer w0.3: R66.2 87.249,152.654 87.718,152.185 C78.2 89.066,151.384 U15.4 90.412,150.61 88.265,148.463 C14.2
NetC15_1: C15.1 R51.2 | length 10.2
  Top Layer w0.3: R51.2@85.725,140.866 R51.2
  Top Layer w0.5: R51.2 85.725,141.986 v2(86.55,142.811) ; v2(89.599,142.748) 92.438,142.748 C15.1
  Bottom Layer w0.3: v2(86.55,142.811) v2@86.614,142.748
  Bottom Layer w0.5: v2@86.614,142.748 v2(89.599,142.748)
NetC15_2: C15.2 C77.1 R62.1 U15.5 | length 16.1
  Top Layer w0.3: C15.2 93.853,148.278 95.262,149.687 U15.5 97.37,151.384 C77.1 99.353,152.439 100.457,153.543 R62.1
NetC16_1: C16.1 R52.2 | length 10.7
  Top Layer w0.5: C16.1 74.168,143.256 74.867,142.558 v2(78.359,142.558) ; v2(81.978,143.129) 82.296,142.811 R52.2
  Bottom Layer w0.5: v2(78.359,142.558) 81.407,142.558 v2(81.978,143.129)
NetC16_2: C16.2 C83.2 R72.2 U16.4 | length 14.6
  Top Layer w0.3: R72.2 69.977,153.289 70.827,152.439 C83.2 72.556,151.384 U16.4 C16.2@74.156,146.951
NetC17_1: C17.1 R59.2 | length 2.8
  Top Layer w0.3: C17.1 79.756,142.836 R59.2
NetC17_2: C17.2 C82.1 R68.1 U16.5 | length 15
  Top Layer w0.3: C17.2 79.756,150.634 U16.5 80.352,151.384 C82.1 81.7,152.185 82.169,152.654 82.169,157.011 R68.1
NetC20_1: C20.1 U11.1 | length 3.8
  Top Layer w0.4: U11.1 v2@91.074,124.254
  Bottom Layer w0.4: v2(91.123,124.206) 92.48,124.206 C20.1
NetC21_1: C21.1 C22.1 R29.1 U11.44 | length 5.4
  Top Layer w0.4: U11.44 v2@89.678,111.204
  Bottom Layer w0.4: v2(89.725,111.252) C22.1 C21.1 R29.1
NetC23_1: C23.1 C24.1 R31.1 U11.23 | length 5.5
  Top Layer w0.4: v2(73.977,111.252) 74.979,111.252 U11.23
  Bottom Layer w0.4: R31.1 C23.1 C24.1 v2(73.977,111.252)
NetC25_1: C25.1 U11.43 | length 4.1
  Top Layer w0.4: v2(88.011,113.157) 88.026,113.142 U11.43
  Bottom Layer w0.4: C25.1 v2@88.162,113.006
NetC25_2: C25.2 L11.2 U11.39 U11.40 | length 50.1
  Top Layer w0.4: U11.39 85.426,113.557 85.725,113.855 ; 85.777,111.204 85.788,111.216 v2(85.788,113.157) ; U11.40 86.077,113.653
  Top Layer w4: 94.043,111.823 117.19,88.677 L11.2
  Bottom Layer w0.4: v2(85.788,113.157) 86.462,112.483 C25.2
NetC27_1: C27.1 U11.34 | length 4.5
  Top Layer w0.4: U11.34 82.177,112.911 v2(82.423,113.157)
  Bottom Layer w0.4: v2(82.423,113.157) 82.907,112.673 C27.1
NetC27_2: C27.2 L12.2 U11.36 | length 18.3
  Top Layer w0.4: U11.36 v2@83.477,113.068
  Top Layer w4: 90.424,87.312 90.424,85.502 L12.2
  Bottom Layer w0.4: v2(83.566,113.157) 84.607,112.116 C27.2
NetC29_1: C29.1 U11.33 | length 4.4
  Top Layer w0.4: v2(81.28,113.157) 81.527,112.91 U11.33
  Bottom Layer w0.4: C29.1 81.05,112.927 v2(81.28,113.157)
NetC29_2: C29.2 L13.2 U11.31 | length 18.2
  Top Layer w0.4: U11.31 v2@80.226,113.068
  Top Layer w4: L13.2 73.215,84.93 73.215,87.503
  Bottom Layer w0.4: C29.2 79.35,112.37 v2(80.137,113.157)
NetC31_1: C31.1 U11.24 | length 4.1
  Top Layer w0.4: U11.24 75.677,113.142 v2(75.692,113.157)
  Bottom Layer w0.4: C31.1 v2@75.795,113.054
NetC31_2: C31.2 L14.2 U11.27 U11.28 | length 50
  Top Layer w0.4: U11.27 77.627,113.762 ; v2(77.915,113.157) 77.915,111.887 77.927,111.875 ; 77.927,111.204 77.927,111.875 ; 77.978,111.823 77.927,111.875 ; U11.28 78.277,113.747
  Top Layer w4: L14.2@46.416,81.026 46.416,88.677 69.563,111.823
  Bottom Layer w0.4: C31.2 77.495,112.737 v2(77.915,113.157)
NetC37_1: C37.1 C41.1 J11.1 L12.1 R34.1 | length 42.8
  Top Layer w4: v1@96.585,56.77 C37.1 100.774,65.151 L12.1
  Bottom Layer w1: J11.1@96.203,51.689 97.597,53.083 C41.1 ; J11.1@97.179,51.269 R34.1
  Bottom Layer w4: J11.1 96.203,51.689 96.203,56.388 C37.1
  other v1: 96.521,56.834 97.757,58.07 98.965,59.277
NetC38_2: C38.2 C42.2 J13.2 L13.1 R35.2 | length 38
  Top Layer w4: L13.1 63.422,65.137 63.422,60.974 v1@67.525,56.871
  Bottom Layer w1: R35.2 J13.2@66.394,51.333 ; C42.2 J13.2@64.58,53.146
  Bottom Layer w4: C38.2 67.435,56.948 J13.2
  other v1: 67.518,56.864 66.311,58.072 65.075,59.308
NetC39_1: C39.1 C43.1 J13.1 L14.1 R36.1 | length 55.2
  Top Layer w4: L14.1 36.386,67.945 v1(47.466,56.864)
  Bottom Layer w1: J13.1@48.475,51.332 R36.1 ; J13.1@50.289,53.147 C43.1
  Bottom Layer w4: C39.1 47.434,56.896 J13.1
  other v1: 46.259,58.072 45.023,59.308
NetC40_2: C40.2 C52.2 J11.2 L11.1 R33.2 | length 61.4
  Top Layer w4: v1@116.665,56.77 127.191,67.296 L11.1
  Bottom Layer w1: R33.2 115.225,51.269 J11.2 116.203,51.943 115.063,53.083 C40.2
  Bottom Layer w4: J11.2 116.203,56.308 C52.2
  other v1: 116.601,56.834 117.837,58.07 119.045,59.277
NetC44_2: C44.2 R33.1 | length 1.8
  Bottom Layer w1: C44.2 R33.1
NetC45_1: C45.1 R34.2 | length 1.8
  Bottom Layer w1: C45.1 R34.2
NetC46_2: C46.2 R35.1 | length 1.8
  Bottom Layer w1: C46.2 R35.1
NetC47_1: C47.1 R36.2 | length 1.8
  Bottom Layer w1: C47.1 R36.2
NetC49_1: C49.1 R37.2 | length 1.8
  Top Layer w1: C49.1 R37.2
NetC53_2: C53.2 C54.2 J22.1 R47.2 U13.2 U13.4 | length 32.7
  Top Layer w0.5: 105.537,164.084 C54.2
  Top Layer w0.6: 105.537,167.259 105.752,167.474 R47.2
  Top Layer w1.2: C53.2 103.505,151.511 105.537,153.543 U13.4 U13.2 105.537,164.084 ; J22.1 105.537,167.259 105.537,164.084 ; 105.594,164.141 105.537,164.084
NetC58_1: C58.1 R40.1 U11.6 | length 17.2
  Top Layer w0.3: U11.6 85.426,127.019 86.804,128.397 86.804,133.16 88.519,134.874 88.519,136.779 87.923,137.375 C58.1 R40.1
NetC59_1: C59.1 R51.1 U11.7 | length 17.3
  Top Layer w0.3: U11.7 84.788,124.265 84.788,127.333 86.106,128.651 86.106,133.096 84.328,134.874 84.328,136.779 84.924,137.375 C59.1 R51.1
NetC60_1: C60.1 R52.1 R201.1 U11.12 | length 18.9
  Top Layer w0.254: C60.1 R52.1 82.78,140.12 83.654,140.994 R201.1
  Top Layer w0.3: U11.12 81.527,133.787 83.146,135.407 83.146,137.668 C60.1
NetC63_2: C63.2 R41.2 R42.1 U12.1 | length 11.4
  Top Layer w0.5: U12.1 63.815,161.669 63.815,162.939 64.96,164.084 C63.2@64.96,167.513 ; 63.815,161.522 R41.2 R42.1
NetC66_1: C66.1 C67.1 J24.1 R73.1 | length 11.7
  Top Layer w0.3: C66.1 J24.1 91.313,174.244 91.909,174.84 R73.1 C67.1
NetC66_2: C66.2 R64.2 | length 3.2
  Top Layer w0.3: R64.2 C66.2
NetC67_2: C67.2 C69.1 J24.3 R73.2 | length 9.8
  Top Layer w0.3: R73.2 C67.2 96.393,171.489 J24.3 96.393,167.767 96.774,167.386 C69.1
NetC68_1: C68.1 C71.1 J25.1 R74.1 | length 12
  Top Layer w0.3: C71.1 74.041,169.545 J25.1 74.549,173.99 75.399,174.84 R74.1 C68.1
NetC68_2: C68.2 C70.1 J25.3 R74.2 | length 9.5
  Top Layer w0.3: R74.2 C68.2 79.629,171.743 J25.3 C70.1
NetC69_2: C69.2 R61.2 | length 3.4
  Top Layer w0.3: R61.2 96.393,163.068 C69.2
NetC70_2: C70.2 R67.2 | length 3.2
  Top Layer w0.3: R67.2 C70.2
NetC71_2: C71.2 R70.2 | length 3.2
  Top Layer w0.3: R70.2 C71.2
NetC72_1: C72.1 R59.1 R200.2 U11.13 | length 21.1
  Top Layer w0.3: C72.1 79.971,138.518 79.756,138.303 79.756,136.207 81.026,134.938 81.026,130.874 80.877,130.724 U11.13
  Top Layer w0.6: R200.2 78.955,139.319 80.772,139.319 ; C72.1 80.772,139.319 ; R59.1 80.772,139.319
NetC73_1: C73.1 R11.1 R39.1 U11.4 | length 15.3
  Top Layer w0.3: U11.4 86.726,126.604 88.219,128.097 88.917,128.097 90.297,129.476 R11.1 89.393,130.483 89.393,132.739 R39.1 90.971,133.643 91.425,134.097 91.425,134.986 91.782,135.343 C73.1
NetC75_1: C75.1 R64.1 R65.2 | length 4.5
  Top Layer w0.3: R65.2 90.981,158.535 R64.1 92.837,158.535 C75.1
NetC75_2: C75.2 R61.1 R63.2 | length 4.5
  Top Layer w0.3: C75.2 96.227,158.369 R61.1 96.725,158.535 R63.2
NetC76_1: C76.1 R70.1 R71.2 | length 4.5
  Top Layer w0.3: R71.2 72.341,160.235 R70.1 75.565,158.535 C76.1
NetC76_2: C76.2 R67.1 R69.2 | length 5
  Top Layer w0.3: C76.2 79.463,158.369 R67.1 79.961,158.535 R69.2
NetC77_2: C77.2 R62.2 R63.1 U15.8 | length 10.7
  Top Layer w0.3: U15.8 97.37,155.194 C77.2 R63.1 100.125,160.235 R62.2
NetC78_1: C78.1 R65.1 R66.1 U15.1 | length 9.6
  Top Layer w0.3: R66.1 87.581,160.235 R65.1 89.281,156.325 U15.1 89.027,155.194 88.265,154.432 C78.1
NetC82_2: C82.2 R68.2 R69.1 U16.8 | length 9.9
  Top Layer w0.3: C82.2 79.844,155.194 U16.8 81.661,157.849 R69.1 81.993,158.535 R68.2
NetC83_1: C83.1 R71.1 R72.1 U16.1 | length 9.6
  Top Layer w0.3: R72.1 70.309,160.235 R71.1 72.009,154.94 ; C83.1 71.501,154.432 72.009,154.94 ; U16.1 72.263,155.194 72.009,154.94
NetD11_1: D11.1 Q11.3 | length 8.4
  Top Layer w0.3: D11.1 59.372,179.514 59.372,177.228 58.547,176.403 58.547,172.875 Q11.3
NetD11_2: D11.2 R43.1 | length 3.5
  Top Layer w0.3: R43.1 57.697,178.767 D11.2
NetD13_2: D13.2 Q13.3 R45.1 | length 8.3
  Top Layer w0.5: D13.2 65.024,177.751 Q13.3 66.068,172.784 R45.1
NetD14_2: D14.2 R46.1 | length 4.6
  Top Layer w0.5: R46.1 114.056,176.11 D14.2
NetD16_2: D16.2 R50.1 | length 2.7
  Top Layer w0.5: R50.1 110.236,177.634 D16.2
NetD18_2: D18.2 L15.1 U17.2 | length 14.3
  Top Layer w1: D18.2 36.244,156.241 U17.2
  Top Layer w2: L15.1 34.604,154.601 D18.2
NetJ19_1: J19.1 R17.2 | length 51.3
  Top Layer w0.5: J19.1 71.148,176.184 71.148,167.769 68.034,164.655 68.034,145.292 76.772,136.555 76.772,135.064 ; R17.2@76.772,133.311 76.772,135.255
NetJ19_2: J19.2 R16.2 | length 50.7
  Top Layer w0.5: J19.2@71.356,178.516 71.848,178.024 71.848,167.479 68.734,164.365 68.734,145.582 78.295,136.021 R16.2@78.295,133.311
NetJ23_2: J23.2 Q14.1 R46.2 R99.1 | length 14.4
  Top Layer w0.5: Q14.1 112.268,173.071 R46.2 116.244,174.41 J23.2
  Bottom Layer w0.5: J23.2 120.738,178.904 R99.1
NetQ11_1: Q11.1 R22.2 | length 2.5
  Top Layer w0.5: Q11.1 R22.2@62.092,174.661
NetQ13_1: Q13.1 R18.2 | length 1.9
  Top Layer w0.3: Q13.1 66.678,175.677 R18.2
NetQ14_3: Q14.3 R11.2 | length 54
  Top Layer w0.3: R11.2 90.297,131.953 90.805,132.461 93.853,132.461 94.615,133.223 94.615,141.034 96.584,143.002 102.997,143.002 109.791,149.796 109.791,157.797 112.649,160.655 112.649,169.89 Q14.3
NetQ16_1: Q16.1 R19.2 | length 4.6
  Top Layer w0.6: Q16.1 109.662,169.191 110.744,168.109 R19.2
NetQ16_3: Q16.3 R48.1 R50.2 | length 7.1
  Top Layer w0.5: R50.2 Q16.3 108.712,169.08 109.093,168.699 R48.1
NetR12_1: R12.1 U11.3 | length 8.4
  Top Layer w0.254: U11.3 87.377,126.392 88.176,127.192 89.155,127.192 89.599,127.635 90.385,127.635
  Top Layer w0.3: 90.385,127.635 R12.1
NetR15_1: R15.1 U11.14 | length 7.5
  Top Layer w0.3: R15.1@79.819,131.611 79.819,130.302 80.226,129.895 U11.14
NetR16_1: R16.1 U11.15 | length 7.9
  Top Layer w0.3: R16.1@78.295,131.611 78.295,130.619 79.577,129.338 U11.15
NetR17_1: R17.1 U11.16 | length 8.2
  Top Layer w0.3: R17.1@76.772,131.611 76.772,130.746 78.926,128.592 U11.16
NetR18_1: R18.1 U11.17 | length 57
  Top Layer w0.3: R18.1 70.549,173.506 70.549,168.148 67.246,164.846 67.246,145.097 75.629,136.715 75.629,130.81 78.277,128.162 U11.17
NetR19_1: R19.1 U11.18 | length 74.8
  Top Layer w0.3: v2(74.739,135.001) 74.739,130.619 77.627,127.732 U11.18 ; v2(93.726,135.255) 93.726,140.97 96.647,143.891 102.552,143.891 108.013,149.352 108.013,158.94 110.998,161.925 110.998,166.028 R19.1
  Bottom Layer w0.3: v2(74.739,135.001) 76.263,135.001 77.66,136.398 85.915,136.398 87.249,137.731 91.249,137.731 v2(93.726,135.255)
NetR22_1: R22.1 U11.19 | length 56.6
  Top Layer w0.3: 75.946,128.46 76.962,127.444 U11.19@76.962,124.015
  Top Layer w0.4: R22.1 63.095,171.958 65.786,171.958 66.611,171.132 66.611,144.907 73.279,138.239 73.279,131.127 75.946,128.46
NetR47_1: R47.1 R48.2 U13.1 | length 8
  Top Layer w0.5: R47.1 R48.2 109.562,165.774 110.109,165.227 110.109,162.941 108.456,161.288 U13.1
NetR75_2: R75.2 U17.5 | length 3.4
  Top Layer w0.5: U17.5 44.665,159.766 R75.2
NetR102_2: R102.2 R202.2 U11.20 | length 19.6
  Top Layer w0.4: R102.2 R202.2 66.954,128.055 66.675,128.333 66.675,130.302 67.564,131.191 71.755,131.191 76.327,126.619 U11.20
NetR103_2: R103.2 R203.2 U11.21 | length 10.1
  Top Layer w0.4: R203.2 v2(69.469,127.127) R103.2 ; v2(74.612,126.682) 75.677,125.618 U11.21
  Bottom Layer w0.4: v2(69.469,127.127) 74.168,127.127 v2(74.612,126.682)
NetR104_2: R104.2 R204.2 U11.22 | length 7.1
  Top Layer w0.4: R104.2 70.929,127.127 ; R204.2 70.929,127.127 ; U11.22 72.154,127.127 70.929,127.127
PVDD: C26.2 C28.2 C30.2 C32.2 C33.2 C34.2 C35.2 C36.2 C48.2 C57.2 C85.2 J12.2 R37.1 U11.25 U11.26 U11.32 U11.35 U11.41 U11.42 U17.1 | length 313.6
  Top Layer w1: U17.1 v2(34.544,164.211) ; C48.2 116.776,154.94 121.029,150.688 123.952,150.688 123.66,150.98 123.66,154.05 R37.1
  Top Layer w1.5: C36.2 71.303,106.172 C32.2 ; 80.711,97.856 C30.2 ; 82.992,97.793 C28.2 ; C26.2 92.4,106.172 C33.2
  Top Layer w1.6: v2(116.205,167.005) 116.205,163.893 122.936,157.162 122.936,150.942 123.336,150.542 J12.2
  Top Layer w2: 77.16,94.305 80.711,97.856 ; 82.992,97.793 86.543,94.241
  Top Layer w3: 52.507,75.177 C36.2 ; 77.16,76.525 C35.2 77.16,94.305 ; 86.543,74.605 C34.2 86.543,94.241 ; 111.196,74.986 C33.2 ; C57.2 J12.2@123.336,150.542 ; J12.2@123.806,150.542 J12.2@123.952,150.688
  Bottom Layer w1.6: v2(34.544,162.179) 34.544,171.45 43.752,180.657 49.784,180.657 ; C85.2 49.784,180.657 ; v2(116.205,164.973) 116.205,173.736 109.283,180.657 49.784,180.657
  other v2: 34.544,163.195 116.205,165.989
VREG: C13.1 R39.2 R103.1 R201.2 R202.1 R204.1 U11.11 | length 42.9
  Top Layer w0.3: U11.11 82.177,126.627 v2(83.33,127.78) 83.693,128.143 C13.1 82.55,130.722 82.55,133.286 83.121,133.858 v2(84.074,133.858) 83.82,134.112 R201.2@83.82,139.167
  Top Layer w0.4: R202.1 R103.1 R204.1 71.54,129.755 v2(73.152,128.143)
  Top Layer w1: R39.2 v4(90.297,136.715)
  Bottom Layer w0.4: v2(73.152,128.143) 82.985,128.143 83.33,127.798 v2(83.33,127.78) ; v2(84.074,133.858) 85.471,133.858 85.979,133.35 87.376,133.35 90.297,136.271 v4(90.297,136.715)
pads on no net: U15.2 U15.7 U16.2 U16.7

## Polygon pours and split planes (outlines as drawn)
GND on Top Layer "TOP_GND" (solid, remove dead copper, pour order 1004): 85.026,112.078 85.026,110.045 85.153,109.918 85.852,109.918 86.296,109.918 88.709,107.505 84.963,107.505 84.963,108.966 84.01,109.918 83.883,110.045 83.883,112.078 85.026,112.078
GND on Top Layer "TOP_GND" (solid, pour order 1003): 78.676,112.078 78.676,110.045 78.549,109.918 77.851,109.918 77.406,109.918 74.993,107.505 78.74,107.505 78.74,108.966 79.692,109.918 79.819,110.045 79.819,112.078 78.676,112.078
PVDD on Top Layer "TOP_PVDD" (solid, pour order 1000): 80.645,112.078 80.645,108.204 79.947,107.505 81.724,107.505 81.724,109.664 81.661,109.728 81.216,109.728 81.09,109.855 81.09,110.553 81.09,112.078 80.645,112.078
PVDD on Top Layer "TOP_PVDD" (solid, pour order 1001): 83.058,112.081 83.058,108.207 83.757,107.509 81.978,107.509 81.978,109.668 82.042,109.731 82.486,109.731 82.614,109.858 82.614,110.557 82.614,112.081 83.058,112.081
PVDD on Top Layer "TOP_PVDD" (solid, pour order 1010): 72.2,107.505 69.977,107.505 51.689,89.218 51.371,88.9 51.371,87.312 53.911,87.312 71.438,104.838 72.2,104.838 72.2,107.505
PVDD on Top Layer "TOP_PVDD" (solid, pour order 1011): 91.519,107.502 93.741,107.502 112.029,89.214 112.347,88.897 112.347,87.309 109.807,87.309 92.281,104.835 91.519,104.835 91.519,107.502
GND on Top Layer "TOP_GND" (solid, pour order 1012): 32.067,182.308 129.731,182.308 129.731,43.878 32.067,43.878 32.067,182.308
NetC31_2 on Top Layer "PWR1" (solid, pour order 1000): 67.31,112.395 72.072,117.157 78.168,117.157 78.486,116.84 78.486,112.522 76.772,112.522 76.772,113.347 76.136,113.983 74.486,113.983 70.104,109.601 67.31,112.395
NetC25_2 on Top Layer "PWR1" (solid, pour order 1001): 96.393,112.395 91.63,117.157 85.534,117.157 85.217,116.84 85.217,112.522 86.931,112.522 86.931,113.347 87.566,113.983 89.218,113.983 93.599,109.601 96.393,112.395
PVDD on Top Layer "PVDD" (solid, pour order 1002): 69.977,107.505 72.263,109.791 75.755,109.791 76.136,110.172 76.11,110.199 76.11,112.078 77.193,112.078 77.216,112.055 77.216,110.016 75.037,107.837 75.037,107.823 74.041,107.823 73.724,107.505 71.438,105.219 71.438,104.838 69.406,106.87 69.406,106.934 69.977,107.505
PVDD on Top Layer "PVDD" (solid, pour order 1003): 93.741,107.502 91.455,109.788 87.963,109.788 87.582,110.169 87.609,110.196 87.609,112.074 86.525,112.074 86.502,112.051 86.502,110.013 88.681,107.834 88.681,107.82 89.677,107.82 89.995,107.502 92.281,105.216 92.281,104.835 94.313,106.867 94.313,106.931 93.741,107.502
NetC29_2 on Top Layer "OUT" (solid, pour order 1004): 80.01,112.014 80.443,112.014 80.443,108.383 80.441,108.381 79.756,107.696 79.756,104.622 79.756,98.87 75.184,94.297 75.184,87.312 71.374,87.312 71.374,96.012 78.93,103.569 78.93,108.902 80.01,109.982 80.01,112.014
NetC27_2 on Top Layer "OUT" (solid, pour order 1005): 83.693,111.982 83.26,111.982 83.26,108.351 83.262,108.349 83.947,107.664 83.947,104.59 83.947,98.838 88.519,94.266 88.519,87.281 92.329,87.281 92.329,95.98 84.773,103.537 84.773,108.871 83.693,109.95 83.693,111.982
PVDD on Top Layer "PVDD" (solid, pour order 1006): 113.728,122.174 113.728,91.854 117.19,88.392 117.19,76.995 117.157,76.962 50.419,76.962 50.419,66.358 125.222,66.358 127.953,69.088 127.953,122.111 127.889,122.174 113.728,122.174
PVDD on Top Layer "PVDD" (solid, pour order 1000): 113.728,122.111 113.728,142.684 117.983,146.939 127.825,146.939 127.889,147.002 127.953,146.939 127.953,122.111 113.728,122.111 113.728,122.174
GND on Bottom Layer "BOT_GND" (solid, pour order 1012): 32.067,182.308 129.731,182.308 129.731,43.878 32.067,43.878 32.067,182.308

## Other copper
Bottom Layer:
  rectangle net GND: 117.729,166.897 119.716,173.418
  region net GND: 126.854,174.18 126.854,176.168 120.332,176.168 120.332,174.18
  region net GND: 129.751,173.005 127.764,173.005 127.764,166.484 129.751,166.484
  region net GND: 121.05,165.671 121.05,163.684 127.572,163.684 127.572,165.671
  region net GND: 122.34,162.286 123.746,163.691 119.134,168.302 117.729,166.897
  region net GND: 126.746,176.53 125.341,175.125 128.335,172.131 129.74,173.536
  region net GND: 122.292,174.952 120.886,176.357 117.892,173.363 119.297,171.958
  region net GND: 129.529,166.297 128.123,167.702 125.129,164.708 126.535,163.303
  rectangle net GND: 84.264,169.736 86.296,171.767

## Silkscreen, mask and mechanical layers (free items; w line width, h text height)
Top Overlay:
  text "OTW" at 112.204,182.308 h1.5 r180
  text "12V Van" at 100.901,181.927 h2 r180
  text "Reset" at 124.46,181.864 h1.5 r180
  text "Sync" at 81.661,181.673 h2 r180
  text "Ready" at 56.896,181.419 h2 r180
  text "-" at 68.072,180.086 h2
  text "+" at 70.612,180.086 h2
  text "-" at 102.298,180.086 h2
  text "+" at 104.838,180.086 h2
  text "Right" at 83.376,178.181 h2 r180
  text "Left" at 96.901,178.181 h2 r180
  text "-   Right   +" at 45.339,48.133 h2
  text "-   Left   +" at 94.932,47.498 h2
Mechanical 1:
  the board outline again, w0.254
